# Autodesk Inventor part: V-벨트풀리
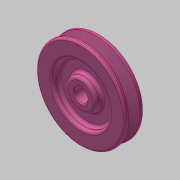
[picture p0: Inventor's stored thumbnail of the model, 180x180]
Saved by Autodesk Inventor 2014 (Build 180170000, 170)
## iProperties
Created: 2020-05
Part Number: V-벨트풀리
Material: 알루미늄 6061
Document SubType Name: Modeling
Designer: mduedu
Density: 1 g/cm^3
Appearance: Pink
Author: mduedu
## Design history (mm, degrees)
sketch "스케치1"
  geometry: L1 (-10, 0)-(10, 0); L2 (10, 47.5)-(-10, 47.5); L3 (-5.976, 47.5)-(-2.154, 35); L4 (-2.154, 35)-(2.154, 35); L5 (2.154, 35)-(5.976, 47.5); L6 (0, 0)-(0, 47.5); L7 (-10, 30)-(-3, 30); L8 (-3, 30)-(-3, 16); L9 (-3, 16)-(-10, 16); L10 (-10, 47.5)-(-10, 30); L11 (-10, 16)-(-10, 0); L12 (10, 30)-(3, 30); L13 (3, 30)-(3, 16); L14 (3, 16)-(10, 16); L15 (10, 0)-(10, 16); L16 (10, 30)-(10, 47.5); L17 (-4.6, 43)-(4.6, 43); 2 further points
  constraints: 34 end point, 6 parallel, 6 perpendicular, 4 point on line, 4 symmetric about line, 3 midpoint, 2 horizontal, 1 coincident, 1 collinear, 1 equal length, 1 vertical alignment
  dimensions: "d0" = 95 diameter of L2 L1; "d2" = 20 distance between parallel lines of L16 L10; "d3" = 6 distance between parallel lines of L13 L8; "d4" = 32 diameter of L14 L1; "d5" = 60 diameter of L12 L1; "d6" = 4.5 distance between parallel lines of L17 L2; "d7" = 8 distance between parallel lines of L4 L17; "d8" = 34 deg angle of L5 L3; "d9" = 9.2 distance of L17.start L17.end
revolve "회전1" sketch "스케치1" stored, may be unused: angle "d10" = 90 deg
sketch "스케치2"
  geometry: L1 (-2.5, 6.538)-(2.5, 6.538); L2 (2.5, 6.538)-(2.5, 9.3); L3 (2.5, 9.3)-(-2.5, 9.3); L4 (-2.5, 9.3)-(-2.5, 6.538); A1 r 7 centre (0, 0) between (-2.5, 6.538) and (2.5, 6.538); 1 further point
  constraints: 8 end point, 2 parallel, 2 point on circle, 1 centre point, 1 coincident, 1 horizontal, 1 perpendicular
  dimensions: "d11" = 14 diameter of A1; "d13" = 16.3 dimension on A1 L3; "d14" = 5 distance of L2.end L3.end
extrude "돌출1" cut sketch "스케치2" stored distance "d15" = 10; taper "d16" = 0 deg
chamfer "모따기1" distance "d17" = 1; stored, may be unused: second distance "d18" = 2, angle "d19" = 45 deg
fillet "모깎기1" dims "d20" = 3
fillet "모깎기2" dims "d21" = 2
fillet "모깎기3" dims "d22" = 1
fillet "모깎기4" dims "d23" = 0.5
fillet "모깎기5" dims "d24" = 3
node "솔리드1"
